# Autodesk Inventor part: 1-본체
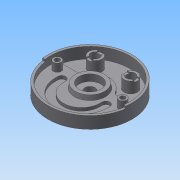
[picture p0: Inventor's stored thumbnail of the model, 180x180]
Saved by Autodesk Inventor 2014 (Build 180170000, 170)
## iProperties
Created: 2015-06
Part Number: 1-본체
Material: Generic
Document SubType Name: Modeling
Designer: Administrator
Density: 1 g/cm^3
Appearance: Default
Author: Administrator
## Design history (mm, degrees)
sketch "스케치1"
  geometry: C1 r 95 at (0, 0); 1 further point
  constraints: 1 centre point, 1 coincident
  dimensions: "d0" = 190 diameter of C1
extrude "돌출1" new body sketch "스케치1" distance "d1" = 32; taper "d2" = 0 deg
sketch "스케치2"
  geometry: L1 (45.033, 16)-(75.657, 16); L2 (-75.657, 16)-(-45.033, 16); C1 r 95 at (0, 0) reference; A1 r 42 centre (0, 0) between (-36.373, 21) and (36.373, 21); A2 r 90 centre (0, 0) between (-85.114, 29.25) and (85.114, 29.25); A3 r 10 centre (-75.657, 26) between (-85.114, 29.25) and (-75.657, 16); A4 r 10 centre (-45.033, 26) between (-45.033, 16) and (-36.373, 21); A5 r 10 centre (45.033, 26) between (36.373, 21) and (45.033, 16); A6 r 10 centre (75.657, 26) between (75.657, 16) and (85.114, 29.25)
  constraints: 12 point on circle, 12 tangent, 6 centre point, 4 end point, 3 equal radius, 2 coincident, 2 horizontal
  dimensions: "d3" = 84 diameter of A1; "d4" = 180 diameter of A2; "d6" = 20 diameter of A3; "d7" = 16 distance from line of C1.centre L2
extrude "돌출2" cut sketch "스케치2" distance "d8" = 25; taper "d9" = 0 deg
extrude "돌출3" cut sketch "스케치2" distance "d10" = 18; taper "d11" = 0 deg
sketch "스케치3"
  geometry: L1 (-75.657, 16)-(-45.033, 16) reference; L2 (-59, -19)-(-59, -14); L3 (-41, -19)-(-41, -14); L4 (41, -19)-(41, -14); L5 (59, -19)-(59, -14); A1 r 90 centre (0, 0) between (-85.114, 29.25) and (85.114, 29.25) reference; A2 r 59 centre (0, -19) between (-59, -19) and (59, -19); A3 r 41 centre (0, -19) between (-41, -19) and (41, -19); A4 r 9 centre (50, -14) between (59, -14) and (41, -14); A5 r 9 centre (-50, -14) between (-41, -14) and (-59, -14); 1 further point
  constraints: 8 end point, 8 point on circle, 6 tangent, 4 centre point, 3 parallel, 2 coincident, 1 perpendicular, 1 vertical alignment
  dimensions: "d12" = 19 distance of point (0, -19) A1.centre; "d13" = 118 diameter of A2; "d14" = 82 diameter of A3; "d15" = 5 vertical distance of A2.centre A5.centre; "d16" = 5 vertical distance of point (0, -19) A4.centre; "d17" = 18 diameter of A5; "d18" = 18 diameter of A4
extrude "돌출4" cut sketch "스케치3" distance "d19" = 7; taper "d20" = 0 deg
sketch "스케치4"
  geometry: C1 r 15 at (-40, 52); C2 r 15 at (40, 52); A1 r 42 centre (0, 0) between (36.373, 21) and (-36.373, 21) reference
  constraints: 2 centre point, 1 equal radius, 1 horizontal alignment
  dimensions: "d21" = 30 diameter of C1; "d22" = 40 horizontal distance of A1.centre C1.centre; "d23" = 80 distance of C2.centre C1.centre; "d24" = 52 vertical distance of A1.centre C2.centre
extrude "돌출5" join sketch "스케치4" stored distance "d25" = 7; taper "d26" = 0 deg
sketch "스케치6"
  geometry: C1 r 15 at (0, 0) reference; C2 r 15 at (80, 0) reference; 3 further points
  constraints: 2 coincident
hole "구멍1" sketch "스케치6" at (0, 0), (80, 0) diameter "d34" = 20; stored, may be unused: countersink angle "d38" = 90 deg, drill point angle "d40" = 118 deg; dims "d35" = 6, "d36" = 4, "d37" = 2, "d39" = 8
sketch "스케치5"
  geometry: L1 (-6, -15)-(6, -15); L2 (6, -15)-(6, 15); L3 (6, 15)-(-6, 15); L4 (-6, 15)-(-6, -15); L5 (-6, -15)-(6, 15); L6 (6, -15)-(-6, 15); L7 (65, 6)-(95, 6); L8 (95, 6)-(95, -6); L9 (95, -6)-(65, -6); L10 (65, -6)-(65, 6); L11 (65, 6)-(95, -6); L12 (95, 6)-(65, -6); C1 r 15 at (0, 0) reference; C2 r 15 at (80, 0) reference; 1 further point
  constraints: 24 end point, 4 midpoint, 4 parallel, 2 horizontal, 2 perpendicular
  dimensions: "d28" = 12 distance of L2.end L3.end; "d29" = 12 distance of L9.end L7.start; "d30" = 30 distance of L1.end L2.end; "d31" = 30 distance of L8.end L9.end
extrude "돌출6" cut sketch "스케치5" distance "d32" = 3; taper "d33" = 0 deg
sketch "스케치7"
  geometry: C1 r 35 at (0, 0); A1 r 42 centre (0, 0) between (36.373, 21) and (-36.373, 21) reference
  constraints: 1 centre point, 1 coincident
  dimensions: "d41" = 70 diameter of C1
extrude "돌출7" join sketch "스케치7" distance "d42" = 10; taper "d43" = -10 deg
sketch "스케치8"
  geometry: C1 r 35 at (0, 0) reference; C2 r 9 at (-74, 0); C3 r 9 at (74, 0)
  constraints: 2 centre point, 2 horizontal alignment, 1 equal radius
  dimensions: "d44" = 18 diameter of C2; "d45" = 148 distance of C3.centre C2.centre; "d46" = 74 distance of C1.centre C3.centre
extrude "돌출8" join sketch "스케치8" distance "d47" = 18; taper "d48" = 0 deg
sketch "스케치9"
  geometry: C1 r 95 at (0, 0) reference; C2 r 26 at (0, 0)
  constraints: 1 centre point, 1 coincident
  dimensions: "d49" = 52 diameter of C2
extrude "돌출9" join sketch "스케치9" distance "d50" = 12; taper "d51" = -15 deg
hole "구멍2" diameter "d54" = 23; stored, may be unused: countersink angle "d58" = 90 deg, drill point angle "d60" = 118 deg; dims "d52" = 10, "d53" = 10, "d55" = 6, "d56" = 50, "d57" = 15, "d59" = 8
sketch "스케치10"
  geometry: C1 r 9 at (-74, 0) reference; C2 r 9 at (74, 0) reference; 2 further points
  constraints: 2 coincident
hole "구멍3" sketch "스케치10" at (-74, 0), (74, 0) diameter "d61" = 11; stored, may be unused: countersink angle "d65" = 90 deg, drill point angle "d67" = 118 deg; dims "d62" = 6, "d63" = 18, "d64" = 11, "d66" = 8
sketch "스케치11"
  geometry: L1 (95, 0)-(90, 0); L2 (0, 0)-(89.124, -12.526); L3 (0, 0)-(-89.124, -12.526); L4 (90, 0)-(-90, 0); L5 (89.124, -12.526)-(94.075, -13.221); L6 (-89.124, -12.526)-(-94.075, -13.221); L7 (-90, 0)-(-95, 0); A1 r 95 centre (0, 0) between (-95, 0) and (-94.075, -13.221) reference; A2 r 90 centre (0, 0) between (90, 0) and (89.124, -12.526) reference
  constraints: 14 end point, 8 point on circle, 3 horizontal, 1 coincident, 1 midpoint, 1 point on line
  dimensions: "d68" = 8 deg angle of L1 L2; "d69" = 8 deg angle of L1 L3; "d70" = 8 deg angle of L7 L6; "d71" = 8 deg angle of L1 L5
extrude "돌출10" cut sketch "스케치11" distance "d72" = 5; taper "d73" = 0 deg
node "솔리드1"
other parameters: "d5" = 16
